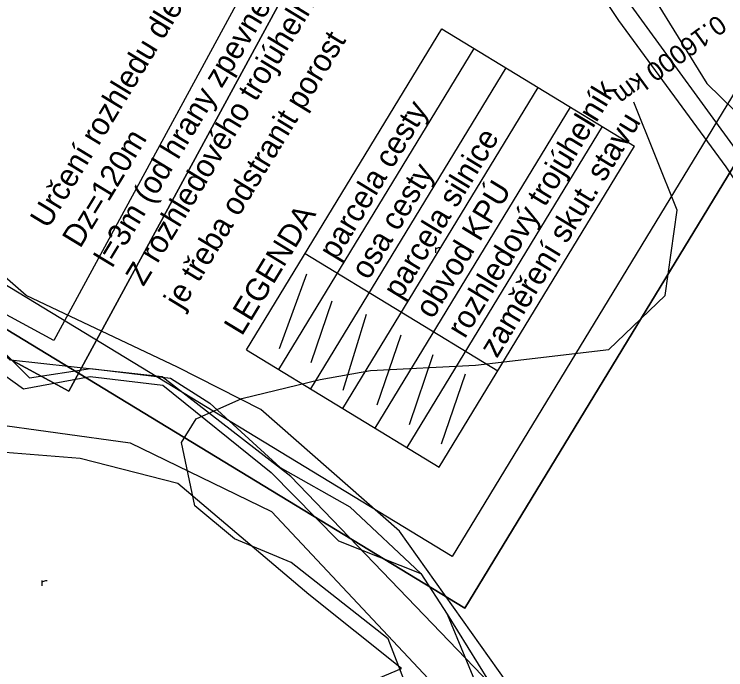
# Model space of a CAD drawing. Extents: x -555887 to -552101, y -1100251 to -1096546.
# Drawn here: x -554029.7 to -553935, y -1097532.1 to -1097444.9 of the extents above; entities that cross this region are included whole.
import ezdxf

# ---------------------------------------------------------------- set-up
doc = ezdxf.new("R2010")
doc.units = 0
for name, color, linetype in [('PARCELY_VHO', 7, 'Continuous'), ('POLYGONY_SITUACE_PF_POPISY', 7, 'Continuous'), ('ROZHLED_ram_legenda_1', 7, 'Continuous'), ('ROZHLED_ram_legenda_2', 7, 'Continuous'), ('vrstevnice', 7, 'Continuous'), ('ZSST', 7, 'Continuous')]:
    doc.layers.add(name, color=color, linetype=linetype)

msp = doc.modelspace()

# ---------------------------------------------------------------- linework, layer by layer
at = {"layer": 'PARCELY_VHO'}
for points in [[(-553890.36, -1097670.23), (-553902.88, -1097642.35), (-553905.32, -1097611.67), (-553898.3, -1097524.98), (-553901.53, -1097506.94), (-553991.85, -1097382.83), (-554027.72, -1097360.75), (-554038.93, -1097345.45), (-554044.87, -1097337.64), (-554055.91, -1097333.12), (-554068.1, -1097310.12), (-554076.3, -1097297.37), (-554083.64, -1097283.44), (-554094.93, -1097256.14), (-554100.02, -1097244.94), (-554114.01, -1097204.34), (-554130.46, -1097180.06), (-554159.17, -1097101.34)], [(-553913.5, -1097649.75), (-553920.52, -1097625.16), (-553955.15, -1097551.67), (-553965.19, -1097535.15), (-553992.85, -1097506.35), (-554009.99, -1097493.12), (-554030.15, -1097490.89), (-554047.7, -1097471.03), (-554054.93, -1097432.75), (-554050.624, -1097409.22), (-554043.26, -1097385.04), (-554052.99, -1097367.96), (-554060.96, -1097387.79), (-554063.97, -1097398.61), (-554064.99, -1097411.72), (-554064.42, -1097434.91), (-554058.01, -1097480.43), (-554033.54, -1097499.24), (-554014.25, -1097501.88), (-553995.42, -1097511.01), (-553971.19, -1097536.91), (-553964.25, -1097552.71), (-553927.41, -1097628.08), (-553920.29, -1097651.1)]]:
    msp.add_lwpolyline(points, dxfattribs=at)
at = {"layer": 'ROZHLED_ram_legenda_1'}
msp.add_lwpolyline([(-554022.385, -1097495.033), (-554206.959, -1097394.87), (-554065.3, -1097133.83), (-553880.726, -1097233.993)], close=True, dxfattribs=at)
msp.add_lwpolyline([(-554022.385, -1097495.033), (-554206.959, -1097394.87), (-554065.3, -1097133.83), (-553880.726, -1097233.993)], close=True, dxfattribs=at)
for points in [[(-553880.726, -1097233.993), (-554065.3, -1097133.83), (-554206.959, -1097394.87), (-554022.385, -1097495.033), (-553880.726, -1097233.993)], [(-554200.18, -1097392.86), (-554063.29, -1097140.609), (-553887.506, -1097236.003), (-554024.395, -1097488.253), (-554200.18, -1097392.86)], [(-554200.18, -1097392.86), (-554063.29, -1097140.609), (-553887.506, -1097236.003), (-554024.395, -1097488.253), (-554200.18, -1097392.86)]]:
    msp.add_lwpolyline(points, dxfattribs=at)
at = {"layer": 'ROZHLED_ram_legenda_2'}
for p, q in [((-553998.74, -1097489.522), (-553972.753, -1097446.806)), ((-553972.753, -1097446.806), (-553947.123, -1097462.398)), ((-553994.468, -1097492.121), (-553968.481, -1097449.404)), ((-553990.197, -1097494.719), (-553964.21, -1097452.003)), ((-553985.925, -1097497.318), (-553959.938, -1097454.602)), ((-553981.653, -1097499.917), (-553955.666, -1097457.2)), ((-553977.382, -1097502.516), (-553951.395, -1097459.799)), ((-553973.11, -1097505.114), (-553947.123, -1097462.398)), ((-553990.944, -1097476.707), (-553965.314, -1097492.299)), ((-553994.364, -1097489.335), (-553990.72, -1097479.401)), ((-553990.153, -1097491.206), (-553987.34, -1097483.003)), ((-553985.886, -1097494.89), (-553982.776, -1097484.777)), ((-553981.353, -1097496.839), (-553978.172, -1097487.514)), ((-553998.74, -1097489.522), (-553973.11, -1097505.114)), ((-553977.082, -1097499.438), (-553973.9, -1097490.113)), ((-553972.81, -1097502.037), (-553969.628, -1097492.711))]:
    msp.add_line(p, q, dxfattribs=at)
msp.add_lwpolyline([(-553994.764, -1097161.002), (-553815.355, -1097270.146), (-553969.717, -1097523.882), (-554149.126, -1097414.737)], close=True, dxfattribs=at)
msp.add_lwpolyline([(-553994.764, -1097161.002), (-553815.355, -1097270.146), (-553969.717, -1097523.882), (-554149.126, -1097414.737)], close=True, dxfattribs=at)
for points in [[(-554149.126, -1097414.737), (-553969.717, -1097523.882), (-553815.355, -1097270.146), (-553994.764, -1097161.002), (-554149.126, -1097414.737)], [(-553822.226, -1097271.819), (-553971.39, -1097517.011), (-554142.255, -1097413.064), (-553993.091, -1097167.872), (-553822.226, -1097271.819)], [(-553822.226, -1097271.819), (-553971.39, -1097517.011), (-554142.255, -1097413.064), (-553993.091, -1097167.872), (-553822.226, -1097271.819)]]:
    msp.add_lwpolyline(points, dxfattribs=at)
at = {"layer": 'vrstevnice'}
msp.add_lwpolyline([(-554022.8, -1097651.574), (-554015.792, -1097639.194), (-554007.167, -1097618.201), (-553999.897, -1097602.433), (-553992.301, -1097589.853), (-553983.593, -1097577.828), (-553975.075, -1097567.183), (-553971.052, -1097558.766), (-553971.244, -1097552.357), (-553972.968, -1097545.948), (-553979.905, -1097527.991), (-553992.816, -1097517.817), (-554000.37, -1097514.66), (-554005.64, -1097510.275), (-554007.396, -1097501.855), (-554005.464, -1097498.698), (-553999.369, -1097495.98), (-553988.959, -1097493.482), (-553982.261, -1097492.273), (-553968.301, -1097491.548), (-553950.547, -1097489.453), (-553943.043, -1097482.281), (-553941.46, -1097470.939), (-553947.224, -1097456.55)], dxfattribs=at)
at = {"layer": 'ZSST'}
for points in [[(-554041.11, -1097397.12), (-554044.32, -1097412.11), (-554048.01, -1097427.93), (-554050.67, -1097444.04), (-554048.27, -1097459.6), (-554042, -1097470.14), (-554037.74, -1097478.62), (-554033.95, -1097486.93), (-554027.65, -1097493.26), (-554019.52, -1097492), (-554008.89, -1097493.27), (-554003.64, -1097496.63), (-553994.28, -1097505.16), (-553985.02, -1097510.4), (-553975.58, -1097519.29), (-553972.07, -1097524.68), (-553966.56, -1097533.56), (-553961.13, -1097544.92), (-553948.08, -1097565.91), (-553939.6, -1097584.69), (-553931.83, -1097597.83), (-553917.93, -1097595.69)], [(-554043.9, -1097398.55), (-554050.26, -1097409.22), (-554054.28, -1097423.2), (-554057.8, -1097443.14), (-554058.38, -1097454.4), (-554057.18, -1097461.11), (-554052.44, -1097467.81), (-554037.74, -1097478.62), (-554035.3, -1097487.51), (-554032.42, -1097491.85), (-554028.44, -1097494.72), (-554019.58, -1097493.05), (-554009.9, -1097494.22), (-553995.49, -1097505.84), (-553986.52, -1097514.94), (-553975.58, -1097519.29)], [(-553958.72, -1097421.9), (-553948.35, -1097436.44), (-553937.52, -1097454.06), (-553924.7, -1097466.6), (-553912.89, -1097484.37), (-553901.31, -1097503.69), (-553895.95, -1097513.08), (-553896.32, -1097532.15), (-553898.08, -1097567.54), (-553899.72, -1097583.35), (-553901.05, -1097601.1), (-553902.42, -1097617.88), (-553903.93, -1097624.37), (-553903.02, -1097629.97), (-553901.18, -1097641.16), (-553898.46, -1097647.37), (-553890.08, -1097660.84), (-553887.03, -1097678.96), (-553881.93, -1097714.48)], [(-553962.7, -1097425.56), (-553949.26, -1097445.69), (-553934.96, -1097465.14), (-553910.73, -1097501.74), (-553903.6, -1097521.64), (-553903.48, -1097523.83), (-553902.42, -1097541.92)], [(-553909.89, -1097591.78), (-553925.72, -1097594.45), (-553929.16, -1097593.49), (-553935.36, -1097582.28), (-553946.09, -1097564.41), (-553958.06, -1097542.29), (-553978.39, -1097513.65), (-553996.86, -1097497.47), (-554007.95, -1097491.83), (-554028.08, -1097482.27), (-554042, -1097470.14)], [(-553973.579, -1097476.616), (-553973.579, -1097475.884)], [(-553973.579, -1097476.12), (-553973.477, -1097476.025), (-553973.374, -1097475.962), (-553973.217, -1097475.915), (-553973.067, -1097475.892), (-553972.91, -1097475.884)], [(-554025.953, -1097520.938), (-554025.953, -1097520.206)], [(-554025.953, -1097520.442), (-554025.851, -1097520.347), (-554025.748, -1097520.284), (-554025.591, -1097520.237), (-554025.441, -1097520.214), (-554025.284, -1097520.206)], [(-553972.07, -1097524.68), (-553967.36, -1097536.06), (-553962.31, -1097548.5), (-553948.08, -1097565.91)]]:
    msp.add_lwpolyline(points, dxfattribs=at)
msp.add_lwpolyline([(-553978.15, -1097531.9), (-553990.46, -1097522.06), (-554007.9, -1097507.29), (-554020.9, -1097503.97), (-554055.31, -1097501.24), (-554051.4, -1097523.62), (-554050.23, -1097534.96), (-554047.61, -1097540.45), (-554037.87, -1097539.41), (-554025.22, -1097538.24), (-553998.77, -1097535.95), (-553983.7, -1097534.25)], close=True, dxfattribs=at)

# ---------------------------------------------------------------- texts
at = {"layer": 'POLYGONY_SITUACE_PF_POPISY'}
msp.add_text('0.16000 km', height=2.5, rotation=216.128, dxfattribs=at).set_placement((-553936.083, -1097444.822))
at = {"layer": 'ROZHLED_ram_legenda_2'}
for s, height, p in [('l=3m (od hrany zpevnění komunikace)', 2.99999, (-554016.627, -1097478.717)), ('Určení rozhledu dle ČSN 73 6101', 2.99999, (-554025.17, -1097473.52)), ('Z rozhledového trojúhelníku', 2.99999, (-554012.474, -1097481.179)), ('je třeba odstranit porost', 2.99999, (-554007.348, -1097484.297)), ('rozhledový trojúhelník', 2.99999, (-553969.709, -1097488.132)), ('parcela cesty', 2.99999, (-553986.796, -1097477.737)), ('zaměření skut. stavu', 2.99999, (-553965.438, -1097490.73)), ('parcela silnice', 2.99999, (-553978.253, -1097482.934)), ('Dz=120m', 3, (-554020.898, -1097476.119)), ('osa cesty', 3, (-553982.524, -1097480.336)), ('obvod KPÚ', 3, (-553973.981, -1097485.533)), ('LEGENDA', 3, (-553999.377, -1097487.779))]:
    msp.add_text(s, height=height, rotation=58.68547, dxfattribs=at).set_placement(p)

doc.saveas('drawing.dxf')
